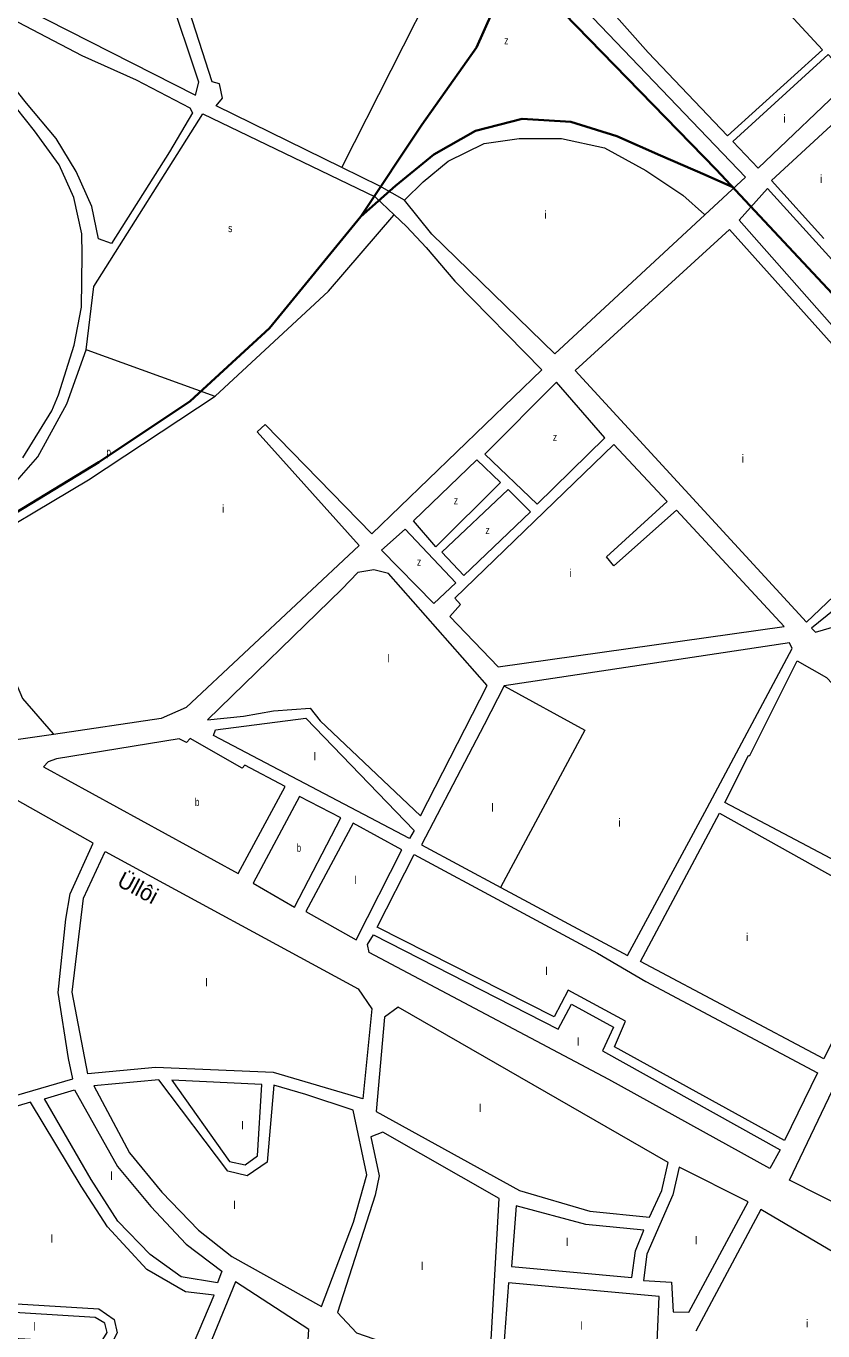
# Model space of a CAD drawing. Extents: x 639657 to 671642, y 222838 to 252123.
# Drawn here: x 654734 to 655731, y 235685 to 237316 of the extents above; entities that cross this region are included whole.
import ezdxf
from ezdxf.enums import TextEntityAlignment as Align

# ---------------------------------------------------------------- set-up
doc = ezdxf.new("R2010")
doc.units = 0
doc.header["$LTSCALE"] = 4
for name, color, linetype, lineweight in [('1', 7, 'Continuous', 13), ('21', 7, 'Continuous', 13), ('57', 7, 'Continuous', 35)]:
    doc.layers.add(name, color=color, linetype=linetype, lineweight=lineweight)
doc.layers.add('22', color=7, linetype='Continuous')
doc.layers.add('7', color=7, linetype='Continuous')

msp = doc.modelspace()

# ---------------------------------------------------------------- linework, layer by layer
at = {"layer": '1'}
msp.add_line((655633.75, 237127.48), (655582.835, 237080.328), dxfattribs=at)
for points in [[(655128.869, 237139.406), (654971.76, 237216.77), (654979.59, 237226.1), (654975.91, 237244.28), (654966.71, 237246.73), (654930, 237360.78), (654929.65, 237372.73), (654935.3, 237385.09), (654966.84, 237412.74), (655025.88, 237483.56), (655060.37, 237539.17), (655068.76, 237568.39), (655071.23, 237598.54), (655071.3, 237617.34), (655143.64, 237624.52), (655178.27, 237636.13), (655198.93, 237647.93), (655210.32, 237664.87), (655252.22, 237750.8), (655259.99, 237762.27), (655325.088, 237735.267)], [(655325.088, 237735.267), (655352.83, 237723.76), (655409.78, 237702.09), (655395.78, 237557.04), (655391.93, 237448.21), (655414.69, 237356.56), (655633.75, 237127.48)], [(654581.38, 237396.12), (654804.03, 237279.67), (654871.96, 237249.11), (654938.91, 237214.23), (654942.3, 237207.87), (654913.42, 237159.34), (654841.04, 237044.72), (654824.79, 237050.23), (654816.26, 237090.85), (654796.9, 237134.43), (654771.7, 237175.71), (654734.6, 237219.93), (654697.44, 237266.29)], [(655731.748, 237050.863), (655666.08, 237123.45), (655783.19, 237231.14), (655815.778, 237197.532), (655934.655, 237074.933), (656084.436, 236920.462), (656127.038, 236876.526)], [(654730.05, 236776.56), (654766.19, 236835.48), (654774.83, 236855.57), (654794.15, 236917.53), (654803.27, 236964.8), (654804.33, 237030.38), (654803.67, 237056.69), (654793.94, 237102.12), (654775.73, 237143.04), (654744.59, 237185.25), (654722.23, 237213.54)], [(654809.43, 236911.77), (654818.74, 236990.98), (654955.22, 237206.58), (655170.58, 237102.84), (655194.273, 237080.293)], [(655207.36, 237098.56), (655176.3, 237116.05), (655128.869, 237139.406)], [(655582.835, 237080.328), (655395.47, 236906.81), (655241.73, 237056.44), (655207.36, 237098.56)], [(655194.273, 237080.293), (655209.65, 237065.66), (655234.48, 237039.41), (655270.46, 236997.32), (655379.06, 236886.64), (655166.55, 236681.51), (655033.12, 236818.44), (655023.14, 236809.06), (655150.79, 236667.15), (654934.46, 236464.62), (654903.1, 236450.95), (654768.538, 236431.028)], [(654438.84, 236603.33), (654440.27, 236632.38), (654470.4, 236630.44), (654515.49, 236632.09), (654573.13, 236648.03), (654628.41, 236671.96), (654676.42, 236707.53), (654719.56, 236744.6), (654748.81, 236778.1), (654785.32, 236844.01), (654809.43, 236911.77)], [(654768.538, 236431.028), (654715.73, 236423.21), (654692.59, 236424.79), (654434.55, 236564.08), (654438.84, 236603.33)], [(655764.06, 236602.64), (655716.336, 236563.854), (655721.445, 236558.742), (655785.399, 236577.458)], [(655327.605, 236239.778), (655486.27, 236154.64), (655585.86, 236339.25), (655692.06, 236538.53), (655688.67, 236545.43), (655332.06, 236491.69), (655307.11, 236442.95)], [(655307.11, 236442.95), (655228.55, 236292.93), (655327.605, 236239.778)], [(655885.74, 235774.25), (655688.91, 235873.69), (655764.427, 236032.486)], [(655897.29, 235455.343), (655979.37, 235535.22), (655905.8, 235659.02), (655869.86, 235642.76), (655854.19, 235666.34), (655883.12, 235686.86), (655858.83, 235715.78), (655653.08, 235836.91), (655571.626, 235684.928)]]:
    msp.add_lwpolyline(points, dxfattribs=at)
for points in [[(654627.3, 237392.18), (654946.15, 237229.85), (654950.04, 237246.06), (654912.27, 237360.07), (654913.29, 237374.94), (654918.52, 237389.23), (654941.62, 237410.75), (654945.63, 237422.13), (654942.15, 237432.25), (654894.85, 237459.45), (654697.28, 237557.76), (654682.1, 237563.29), (654667.02, 237565.06), (654649.89, 237562.48), (654496.77, 237516.88), (654463.4, 237519.26), (654418.52, 237535.24), (654379.14, 237563.26), (654314.56, 237546.61), (654479.4, 237463.7)], [(655730.21, 237286.76), (655482.26, 237554.55), (655431.09, 237559.72), (655420, 237445.01), (655421.75, 237418.19), (655435.62, 237379.32), (655459.65, 237342.32), (655512.17, 237283.46), (655611.28, 237178.99)], [(655617.9, 237172.02), (655737.016, 237280.734), (655766.07, 237249.51), (655649.59, 237138.62)], [(656014.666, 236633.283), (655625.662, 237073.782), (655661.422, 237113.401), (656031.784, 236704.436)], [(655420.61, 236885.67), (655613.9, 237061.98), (655895.37, 236747.51), (655710.05, 236571.21)], [(655397.35, 236871.23), (655307.74, 236781.42), (655373.1, 236718.62), (655457.95, 236801.6)], [(655469.15, 236793.51), (655270.36, 236601.05), (655277.54, 236593.18), (655263.95, 236578.33), (655324.27, 236515.35), (655682.25, 236565.68), (655547.5, 236711.13), (655469.2, 236641.48), (655459.78, 236653.06), (655535.95, 236722.12)], [(655327.43, 236745.92), (655246.72, 236665.47), (655218.5, 236698.07), (655297.71, 236774.19)], [(655364.84, 236709.36), (655336.79, 236737.02), (655253.87, 236658.66), (655281.42, 236629.62)], [(655271.49, 236620.42), (655208.02, 236687.6), (655178.6, 236661.08), (655244.2, 236594.49)], [(655128.78, 236612.56), (654960.96, 236449.35), (655005.98, 236453.7), (655043.41, 236460.54), (655089.53, 236463.84), (655101.75, 236448.03), (655227.51, 236329.07), (655310.88, 236491.92), (655187.38, 236632.29), (655169, 236636.67), (655149.2, 236633.48)], [(655821.7, 236232.86), (655607.72, 236345.71), (655637.41, 236404.47), (655639.02, 236404.51), (655698.36, 236523.1), (655734.89, 236501.99), (655883.87, 236345.62), (655871.66, 236318.45), (655865.15, 236320.98)], [(655213.43, 236300.94), (654968.44, 236429.66), (654970.95, 236436.7), (655083.94, 236451.35), (655219.63, 236310.76)], [(654756.13, 236390.51), (654999.18, 236257.13), (655058.15, 236365.82), (655007.52, 236392.49), (655004.39, 236388.65), (654939.53, 236425.71), (654934.81, 236420.76), (654925.57, 236425.36), (654772, 236400.58), (654761.89, 236396.56)], [(654612.33, 235947.82), (654792.55, 236000.62), (654787.28, 236025.84), (654774.37, 236108.54), (654784.02, 236199.84), (654789.39, 236231.53), (654818.16, 236295.16), (654707.17, 236357.71), (654678.16, 236333.54), (654573.98, 236146.61), (654570.23, 236110.63), (654588.43, 236023.54)], [(655018.21, 236245.02), (655069.99, 236215.16), (655127.9, 236326.73), (655076.19, 236353.38)], [(655778.32, 236120.57), (655731.82, 236025.4), (655502.58, 236146.99), (655601.07, 236332.65), (655821.21, 236209.75)], [(655084.1, 236209.6), (655146.78, 236174.1), (655204.12, 236286.73), (655143.11, 236320.13)], [(654896.14, 236014.74), (654811.45, 236006.5), (654791.85, 236108.71), (654806.07, 236226.05), (654832.97, 236284.45), (655149.34, 236112.95), (655166.46, 236087.87), (655155.17, 235975.48), (655043.38, 236008.38)], [(655682.31, 235923.32), (655470.08, 236040.59), (655483.5, 236072.38), (655412.17, 236111.09), (655394.66, 236077.86), (655173.25, 236189.8), (655219.32, 236280.67), (655448.59, 236157.46), (655509.12, 236121.91), (655723.75, 236008.06)], [(655664, 235888.23), (655462.75, 235999.59), (655163.29, 236158.39), (655160.89, 236168.54), (655168.64, 236180.55), (655399.51, 236062.66), (655416.16, 236093.76), (655468.52, 236065.04), (655455, 236035.6), (655677.11, 235911.69)], [(655529, 235860.87), (655537.22, 235896.01), (655199.31, 236089.87), (655182.44, 236077.51), (655171.91, 235959.59), (655351.05, 235860.87), (655439.22, 235835.01), (655513.63, 235827.72)], [(654986.41, 235884.92), (654899.99, 235999.25), (654819.04, 235991.6), (654863.43, 235907.97), (654903.93, 235858.71), (654949.79, 235811.08), (654991.3, 235778.48), (655103.59, 235715.98), (655143.56, 235821.34), (655160.3, 235880.48), (655143.02, 235961.07), (655083.94, 235980.84), (655043.92, 235992.49), (655035.43, 235896.29), (655010.44, 235879.37)], [(655029.13, 235993.49), (654916.48, 235998.77), (654988.68, 235897.18), (655008.28, 235893.05), (655023.58, 235904.3)], [(654707.5, 235662.97), (654730.86, 235599.13), (654918.99, 235584.82), (654923.68, 235621.91), (654969.46, 235730.05), (654933.44, 235734.21), (654884.97, 235761.95), (654835.86, 235815.48), (654802.88, 235866.38), (654739.58, 235971.37), (654617.22, 235934.95), (654688.07, 235721.26), (654825.33, 235712.84), (654844.38, 235699.49), (654848.21, 235682.85), (654839.47, 235666), (654818.78, 235660.11)], [(654815.74, 235874.49), (654757.31, 235975.24), (654794.91, 235986.55), (654848.46, 235890.73), (654890.03, 235840.93), (654934.28, 235793.84), (654979.01, 235760.17), (654973.45, 235745.56), (654927.99, 235752.99), (654889.19, 235780.77), (654848.73, 235822.51)], [(655325.78, 235850.68), (655180.36, 235933.91), (655165.34, 235927.95), (655175.75, 235879.1), (655170.56, 235854.97), (655123.58, 235708.22), (655147.51, 235682.94), (655221.77, 235656.9), (655299.72, 235647.54), (655314.72, 235659.41)], [(655636.92, 235846.52), (655550.91, 235889.81), (655542.84, 235855.61), (655510.17, 235781.42), (655506.2, 235748.25), (655541.3, 235746.16), (655543.22, 235709.33), (655562.78, 235708.72)], [(655434.07, 235818.25), (655346.77, 235841.63), (655341.16, 235765.87), (655491.67, 235751.95), (655496.38, 235785.27), (655506.71, 235811.41)], [(655087.78, 235687.23), (654995.93, 235746.69), (654943.66, 235618.83), (654938.86, 235588.12), (655079.33, 235559.37)], [(655525.62, 235728.45), (655337.48, 235745.44), (655329.82, 235645.5), (655521.7, 235633.36)], [(654832.83, 235694.89), (654820.73, 235702.29), (654692.27, 235710.18), (654703.15, 235676.92), (654813.35, 235670.88), (654830.05, 235674.42), (654835.5, 235683.44)]]:
    msp.add_lwpolyline(points, close=True, dxfattribs=at)
at = {"layer": '21'}
for points in [[(655325.088, 237735.267), (655325.049, 237734.767), (655313.298, 237585.814), (655251.462, 237382.127), (655129.122, 237139.906), (655128.869, 237139.406)], [(655207.36, 237098.56), (655207.86, 237099.053), (655230.85, 237121.717), (655261.768, 237147.5), (655306.857, 237169.416), (655350.657, 237175.862), (655403.475, 237175.862), (655457.582, 237164.259), (655509.112, 237135.898), (655555.489, 237104.958), (655582.336, 237080.778), (655582.835, 237080.328)], [(654970.623, 236853.573), (655112.331, 236985.067), (655193.843, 237079.793), (655194.273, 237080.293)], [(654809.43, 236911.77), (654809.93, 236911.589), (654970.123, 236853.754), (654970.623, 236853.573)], [(654653.714, 236655.042), (654812.169, 236749.151), (654970.623, 236853.573)], [(654653.714, 236655.042), (654653.926, 236654.542), (654729.72, 236475.85), (654768.105, 236431.528), (654768.538, 236431.028)], [(655332.06, 236491.69), (655332.56, 236491.414), (655432.817, 236436.052), (655327.873, 236240.278), (655327.605, 236239.778)]]:
    msp.add_lwpolyline(points, dxfattribs=at)
at = {"layer": '57'}
for points in [[(655194.015, 238248.902), (655292.399, 238244.46), (655355.87, 238224.139), (655419.342, 238165.715), (655432.037, 238114.912), (655376.181, 237721.189), (655353.332, 237576.401), (655353.332, 237457.014), (655373.643, 237378.269), (655406.648, 237332.547), (655597.063, 237136.955), (656008.36, 236697.51), (656070.563, 236632.736), (656288.906, 236411.743), (656545.331, 236205.991), (656771.291, 236025.64), (656852.535, 235959.596), (656992.172, 235863.071), (657124.194, 235784.326), (657157.833, 235765.91), (657427.225, 235685.806)], [(655353.332, 237457.014), (655335.56, 237375.729), (655297.477, 237289.364), (655228.927, 237192.838), (655152.761, 237078.531), (655038.512, 236938.823), (654939.496, 236847.378), (654825.247, 236771.173), (654683.07, 236684.808), (654548.51, 236613.684), (654442.513, 236566.057), (654386.657, 236538.115), (654205.128, 236445.4), (653995.671, 236346.334)], [(655152.761, 237078.531), (655195.922, 237116.634), (655244.16, 237156.006), (655296.207, 237185.218), (655354.601, 237200.459), (655415.534, 237196.648), (655472.659, 237178.867), (655527.244, 237154.736), (655583.099, 237130.605), (655617.759, 237114.842)]]:
    msp.add_lwpolyline(points, dxfattribs=at)

# ---------------------------------------------------------------- texts
at = {"layer": '22'}
msp.add_text('Üllôi', height=20, rotation=331.98, dxfattribs=at).set_placement((654869.397, 236230.348), align=Align.CENTER)
at = {"layer": '7'}
for s, width, p in [('z', 0.8, (655332.002, 237293.424)), ('s', 0.8, (654986.753, 237058.797)), ('z', 0.8, (655392.807, 236797.608)), ('p', 0.75, (654834.74, 236779.05)), ('z', 0.8, (655268.927, 236718.371)), ('z', 0.8, (655308.517, 236681.308)), ('z', 0.8, (655222.951, 236641.69)), ('b', 0.75, (654945.248, 236341.42)), ('b', 0.75, (655072.536, 236284.27))]:
    msp.add_text(s, height=10, dxfattribs=dict(at, width=width)).set_placement(p)
for s, p in [('i', (655681.05, 237195.766)), ('i', (655727.026, 237120.363)), ('i', (655382.244, 237075.556)), ('i', (655629.073, 236770.769)), ('i', (654979.024, 236708.147)), ('i', (655413.241, 236627.632)), ('l', (655185.627, 236521.121)), ('l', (655093.675, 236398.432)), ('l', (655315.892, 236334.531)), ('i', (655474.543, 236315.796)), ('l', (655144.759, 236243.792)), ('i', (655634.182, 236172.658)), ('l', (655383.579, 236130.049)), ('l', (654958.253, 236115.968)), ('l', (655423.169, 236041.866)), ('l', (655300.567, 235958.795)), ('l', (655003.186, 235937.28)), ('l', (654839.45, 235874.164)), ('l', (654993.124, 235837.575)), ('l', (654764.947, 235795.578)), ('l', (655409.302, 235791.548)), ('l', (655570.391, 235793.563)), ('l', (655228.077, 235761.322)), ('l', (654742.994, 235685.759)), ('l', (655427.424, 235686.766)), ('i', (655709.276, 235689.682))]:
    msp.add_text(s, height=10, dxfattribs=at).set_placement(p)

doc.saveas('drawing.dxf')
